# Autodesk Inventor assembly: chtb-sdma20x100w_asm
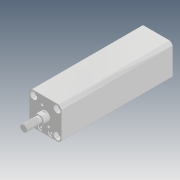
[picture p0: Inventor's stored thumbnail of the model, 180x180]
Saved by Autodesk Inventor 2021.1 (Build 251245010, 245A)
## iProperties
Company: Microsoft
Created: 2018-05
Part Number: chtb-sdma20x100w_asm
Description: STEP AP214
Document SubType Name: Assembly
Designer: user
Title: chtb-sdma20x100w_asm.STEP
Author: Windows
Revision Number: ÈÎºÎ
Sending System: SolidWorks 2015
Preprocessor: SwSTEP 2.0
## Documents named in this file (4)
- D:\Vault_2016\Projekty\Clamptek\Hydraulic\CHTB\CHTB-20\Inventor\CHTB-SDMA20x100W\chtb-sdma20x100w_asm.iam
- D:\Vault_2016\Projekty\Clamptek\Hydraulic\CHTB\CHTB-20\Inventor\CHTB-SDMA20x100W\CHTB-SDMA20X100NBT.ipt
- D:\Vault_2016\Projekty\Clamptek\Hydraulic\CHTB\CHTB-20\Inventor\CHTB-SDMA20x100W\CHTB-SDMA20X100WHSG.ipt
- D:\Vault_2016\Projekty\Clamptek\Hydraulic\CHTB\CHTB-20\Inventor\CHTB-SDMA20x100W\QG_3.ipt
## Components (3 placed, 3 different names)
1. CHTB-SDMA20X100NBT_1
2. CHTB-SDMA20X100WHSG_2
3. QG_3_3
